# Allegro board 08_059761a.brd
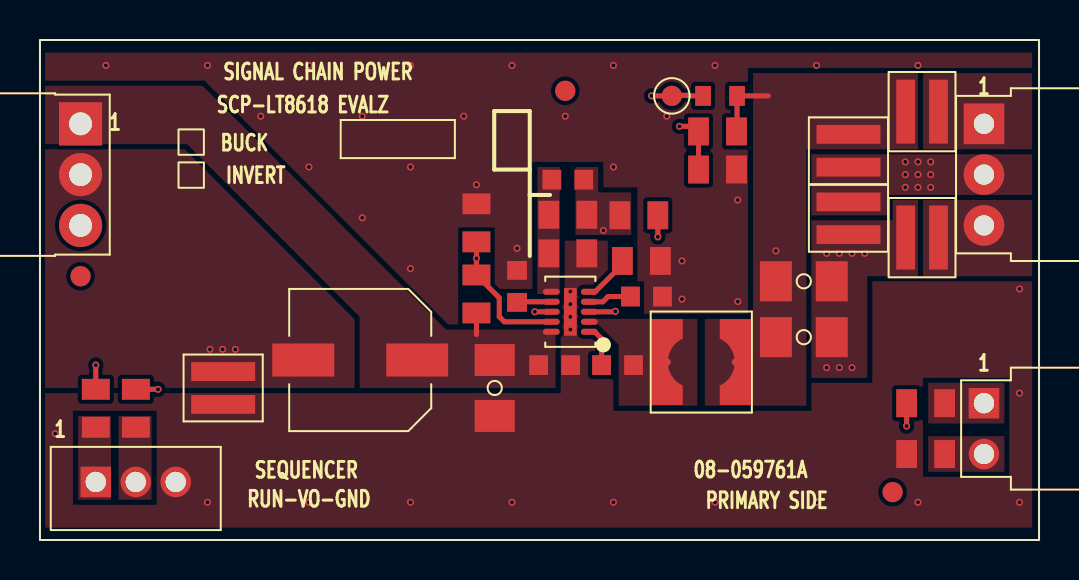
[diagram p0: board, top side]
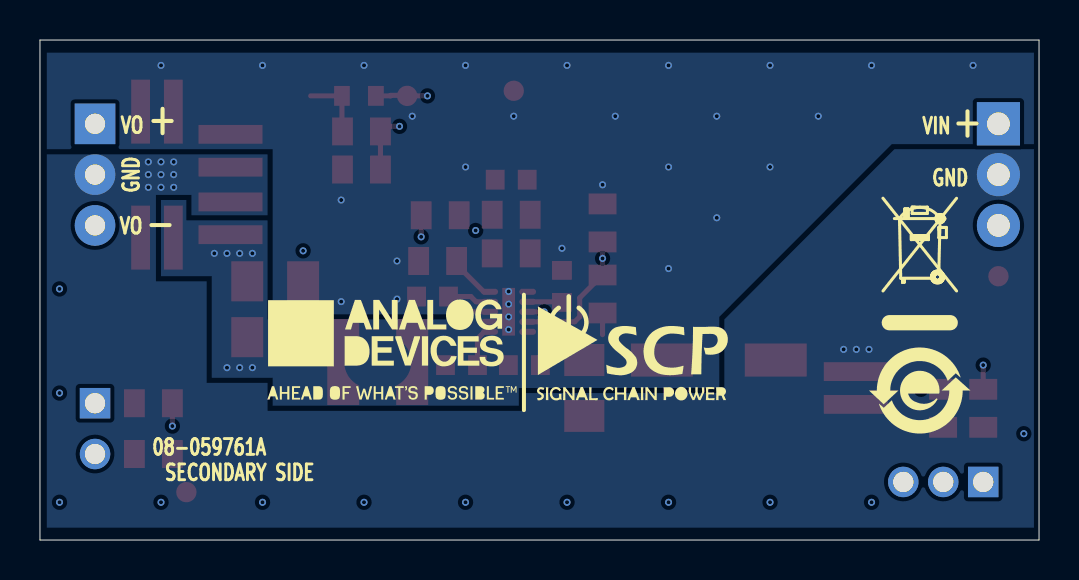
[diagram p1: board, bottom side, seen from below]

Outline 50 x 25 mm; copper layers: TOP, L2_GND, L3_SIGNAL, BOTTOM. Coordinates in mm from the lower left corner of the outline.
Outline path: 0,25 50,25 50,0 0,0 0,25

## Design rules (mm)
constraint set DEFAULT: min track width 0.254

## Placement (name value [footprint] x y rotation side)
C1  22UF  [CPLSMSQ260H315]  16.03 9 180 top
C2  1uF  [C1206H71]  22.76 7.6 270 top
C3  0.1UF  [C0603]  25.76 8.74 0 top
C4  0.047uF  [C0603]  28.91 8.74 0 top
C5  TBD0603  [C0603]  26.42 18.02 0 top
C6  10UF  [C1206H71]  38.23 10.14 0 top
C7  1UF  [C0603]  30.35 12.17 0 top
C8  0.01uF  [C0603]  23.88 12.68 90 top
C9  4.7UF  [C1206H71]  38.23 12.94 0 top
INPUT  PBC03SBAN  [CNTHMHDRRA1X3L300W100H145]  2.03 20.81 270 top
L1  33UH  [LSMSQ150H71]  33.1 8.9 0 top
NOREF  -  []  50 0 90 top
NOREF#2  -  [unnamed#2]  2.03 13.19 0 top
NOREF#3  -  []  90.79 32.31 0 top
NOREF#4  -  []  50 25 0 top
NOREF#5  -  []  0 0 0 top
NOREF#6  -  []  -137.31 -48.38 0 top
NOREF#7  -  []  -197.25 -222.03 0 top
NOREF#8  -  []  50 0 90 top
NOREF#9  -  []  0 0 0 top
NOREF#10  -  []  0 25 0 top
NOREF#11  -  []  50 25 180 top
NOREF#12  -  []  2.03 20.81 0 top
NOREF#13  -  [unnamed#2]  42.67 2.39 0 top
NOREF#14  -  []  -131.19 155.48 0 top
NOREF#15  -  []  77.05 131.34 0 top
NOREF#16  -  []  0 0 0 top
NOREF#17  -  []  44.53 3.99 0 top
NOREF#18  -  [unnamed#2]  26.29 22.46 0 top
NOREF#19  -  []  -197.25 -222.03 0 top
NOREF#20  -  []  0 25 0 top
NOREF#21  -  []  0 25 270 top
NOREF#22  -  []  2.03 20.81 0 top
NOREF#23  -  []  25.51 46.03 0 top
NOREF#24  -  []  -197.25 -222.03 0 top
NOREF#25  -  []  32.67 9.48 180 bottom
NOREF#26  -  []  5.97 7.47 180 bottom
NOREF#27  -  []  6.17 10.55 180 bottom
NOREF#28  -  []  17.55 11.26 180 bottom
NOREF#29  -  []  20.32 9.63 180 bottom
OUTPUT  PPPC031LGBN-RC  [CNHDRRA1X3H108]  47.24 20.81 270 top
P1  53253-0370  [CNTHMHDR1X3L315W144H224]  2.79 2.9 0 top
PG  TESTPAD  [TPSMC40]  31.62 22.21 0 top
R1  1MEG  [R0805]  21.84 12.3 90 top
R2  18.2K  [R0805]  30.1 13.95 0 top
R3  49.9K  [R0603]  34.04 22.21 180 top
R4  1MEG  [R0805]  26.42 16.26 0 top
R5  187K  [R0805]  26.42 14.33 0 top
R6  TBD0805  [R0805]  21.84 15.86 90 top
R7  0  [R0805]  29.97 16.24 180 top
R8  TBD0805  [R0805]  44.32 6.84 0 top
R9  0  [R0805]  33.91 20.43 180 top
R10  TBD0805  [R0805]  33.91 18.52 0 top
R11  TBD0805  [R0805]  2.79 6.59 90 top
R12  TBD0805  [R0805]  4.8 6.59 90 top
R13  TBD0805  [R0805]  44.32 4.3 0 top
R14  0  [R0612]  9.17 7.6 270 top
R15  0  [R0612]  40.46 16.08 90 top
R16  0  [R0612]  44.15 21.42 0 top
R17  0  [R0612]  40.46 19.46 270 top
R18  0  [R0612]  44.15 15.12 0 top
U1  LT8618EDDB#PBF  [DFN10_3X2_PAD2_39X0_64]  26.54 11.41 90 top
VIOC  PPPC021LGBN-RC  [CNTHFHDRRA1X2L220W335H108]  47.24 6.84 270 top

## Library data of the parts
C1 = CAPP: Tolerance: 20; User Part Number: UPN; alternate symbols: (); part number: CAPP_SM-22UF,63V,20,E033596,CPLSMSQ260H315; tolerance: 20
C2 = CAP: Tolerance: 10; User Part Number: UPN; alternate symbols: (); part number: CAP_SM-1UF,100V,10,E023069,C1206H71; tolerance: 10
C3 = CAP: User Part Number: UPN; Tolerance: 10; alternate symbols: (C0603L); part number: CAP_SM-0.1UF,100V,10,E033337,C0603; tolerance: 10
C4 = CAP: User Part Number: UPN; Tolerance: 10; alternate symbols: (); part number: CAP_SM-0.047UF,50V,10,E012649,C0603; tolerance: 10
C5 = CAP: User Part Number: UPN; alternate symbols: (C0603L, C0603L_ALT); part number: CAP_SM-TBD0603,TBD0603,TBD0603,E000382,C0603
C6 = CAP: Tolerance: 20; User Part Number: UPN; alternate symbols: (); part number: CAP_SM-10UF,50V,20,E035601,C1206H71; tolerance: 20
C7 = CAP: User Part Number: UPN; Tolerance: 10; alternate symbols: (); part number: CAP_SM-1UF,10V,10,E033698,C0603; tolerance: 10
C8 = CAP: User Part Number: UPN; Tolerance: 10; alternate symbols: (); part number: CAP_SM-0.01UF,50V,10,E018587,C0603; tolerance: 10
C9 = CAP: Tolerance: 10; User Part Number: UPN; alternate symbols: (); part number: CAP_SM-4.7UF,50V,10,E038262,C1206H71; tolerance: 10
INPUT = CN3P: Tolerance: N/A; User Part Number: UPN; alternate symbols: (CNTHMHDRRA1X3L300W100H145_SCP); part number: CN3P_TH-PBC03SBAN,E034137,CNTHMHDRRA1X3L300W100H145; tolerance: N/A
L1 = IND: User Part Number: UPN; Tolerance: 30; alternate symbols: (); part number: IND_SM-33UH,30,E040015,LSMSQ150H71; tolerance: 30
OUTPUT = CN3P: User Part Number: UPN; Tolerance: N/A; alternate symbols: (CNHDRRA1X3H108_SCP); part number: CN3P_TH-PPPC031LGBN-RC,E034111,CNHDRRA1X3H108; tolerance: N/A
P1 = CN3P: Tolerance: N/A; User Part Number: UPN; alternate symbols: (); part number: CN3P_TH-53253-0370,E033940,CNTHMHDR1X3L315W144H224; tolerance: N/A
PG = NCTESTPAD: Tolerance: N/A; User Part Number: UPN; alternate symbols: (); part number: NCTESTPAD_SM-TESTPAD,E019801,TPSMC40; tolerance: N/A
R1 = RES: User Part Number: UPN; Tolerance: 5; alternate symbols: (); part number: RES_SM-1MEG,E033749,1/8W,5,R0805; tolerance: 5
R2 = RES: User Part Number: UPN; Tolerance: 1; alternate symbols: (R0805L); part number: RES_SM-18.2K,E020752,1/8W,1,R0805; tolerance: 1
R3 = RES: User Part Number: UPN; Tolerance: 1; alternate symbols: (R0603L); part number: RES_SM-49.9K,E015342,1/10W,1,R0603; tolerance: 1
R4 = RES: User Part Number: UPN; Tolerance: 1; alternate symbols: (R0805L); part number: RES_SM-1MEG,E003518,1/8W,1,R0805; tolerance: 1
R5 = RES: User Part Number: UPN; Tolerance: 1; alternate symbols: (R0805L); part number: RES_SM-187K,E015129,1/8W,1,R0805; tolerance: 1
R6 R8 R10-R13 = RES: User Part Number: UPN; alternate symbols: (R0805L); part number: RES_SM-TBD0805,E004051,TBD0805,TBD0805,R0805
R7 R9 = RES: User Part Number: UPN; Tolerance: N/A; alternate symbols: (R0805L); part number: RES_SM-0,E030875,1/8W,N/A,R0805; tolerance: N/A
R14-R18 = RES: User Part Number: UPN; Tolerance: N/A; alternate symbols: (); part number: RES_SM-0,E034651,3/4W,N/A,R0612; tolerance: N/A
U1 = ADLT8618: User Part Number: UPN; Tolerance: N/A; alternate symbols: (); part number: ADLT8618_SM-LT8618EDDB#PBF,E039888,DFN10_3X2_PAD2_39X0_64; tolerance: N/A
VIOC = CN2P: Tolerance: N/A; User Part Number: UPN; alternate symbols: (CNTHFHDRRA1X2L220W335H108_SCP); part number: CN2P_TH-PPPC021LGBN-RC,E034113,CNTHFHDRRA1X2L220W335H108; tolerance: N/A

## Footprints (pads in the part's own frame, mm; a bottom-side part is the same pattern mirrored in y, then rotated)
C0603
  rect 0.94x0.991 smd: 1(-0.8,0) 2(0.8,0)
C1206H71
  rect 1.6x2.007 smd: 1(-1.397,0) 2(1.397,0)
CNHDRRA1X3H108
  rect 2.032x2.032 hole 1.016: 1(0,0)
  round 2.032 hole 1.016: 2(2.54,0) 3(5.08,0)
CNTHFHDRRA1X2L220W335H108
  rect 1.524x1.524 hole 1.016: 1(0,0)
  round 1.524 hole 1.016: 2(2.54,0)
CNTHMHDR1X3L315W144H224
  rect 1.524x1.524 hole 1.016: 1(0,0)
  round 1.524 hole 1.016: 2(2,0) 3(4,0)
CNTHMHDRRA1X3L300W100H145
  rect 2.159x2.159 hole 1.143: 1(0,0)
  round 2.159 hole 1.143: 2(2.54,0) 3(5.08,0)
CPLSMSQ260H315
  rect 3.099x1.651 smd: N(2.85,0) P(-2.85,0)
DFN10_3X2_PAD2_39X0_64
  oval 0.305x0.838 smd: 1(-1,-0.95) 2(-0.5,-0.95) 3(0,-0.95) 4(0.5,-0.95) 5(1,-0.95) 6(1,0.95) 7(0.5,0.95) 8(0,0.95) 9(-0.5,0.95) 10(-1,0.95)
  rect 2.388x0.635 smd: PAD(0,0)
LSMSQ150H71
  custom 0.4x0.4 smd: 1(-1.725,0) 2(1.725,0)
R0603
  rect 0.787x0.991 smd: 1(-0.85,0) 2(0.85,0)
R0612
  rect 0.94x3.2 smd: 1(-0.82,0) 2(0.82,0)
R0805
  rect 1.041x1.397 smd: 1(-0.95,0) 2(0.95,0)
TPSMC40
  round 1.016 smd: 1(0,0)
unnamed#2
  round 1.016 smd: (0,0)

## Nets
GND: C1.N(N2) INPUT.2 OUTPUT.2 R14.1 R15.2(N2) R17.2(N2)
BIAS: R9.2(N2) R10.1 U1.3
PG: PG.1(N1) R3.2(N2) U1.8
RUN: P1.1 R11.1
UNNAMED_2_ADLT8618_I2_BST: C4.1 U1.1
UNNAMED_2_ADLT8618_I2_EN: R1.2(N2) R6.1 R11.2(N2) U1.9
UNNAMED_2_ADLT8618_I2_FB: C5.1 R4.1 R5.1 U1.6
UNNAMED_2_ADLT8618_I2_INTVCC: C7.1 U1.4
UNNAMED_2_ADLT8618_I2_RT: R2.1 U1.5
UNNAMED_2_ADLT8618_I2_SW: C4.2(N2) L1.1 U1.2
UNNAMED_2_ADLT8618_I2_TR: C8.1 U1.7
UNNAMED_2_CAP_I43_N2: C5.2(N2) R4.2(N2) R7.2(N2) R8.1
UNNAMED_2_CN2P_I35_N2: R13.2(N2) VIOC.2(N2)
UNNAMED_2_CN3P_I39_N2: P1.2 R12.1
V+: C1.P C2.1 C3.1 INPUT.1 R1.1 U1.10(VIN)
VIOC: R8.2(N2) VIOC.1
VNEG: C2.2(N2) C3.2(N2) C6.2(N2) C7.2(N2) C8.2(N2) C9.2(N2) P1.3(N3) R2.2(N2) R5.2(N2) R6.2(N2) R10.2(N2) R13.1 R14.2(N2) R15.1 R18.1 U1.PAD
VO+: OUTPUT.1 R12.2(N2) R16.2(N2)
VO-: OUTPUT.3(N3) R18.2(N2)
VPOS: C6.1 C9.1 L1.2(N2) R3.1 R7.1 R9.1 R16.1 R17.1

Pads without a net: INPUT 3

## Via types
v1: diameter 0.356, hole 0.203, TOP to BOTTOM, 71 vias

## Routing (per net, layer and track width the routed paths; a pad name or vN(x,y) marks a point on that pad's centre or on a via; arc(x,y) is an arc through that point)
GND:
  vias: v1(8.51,9.53) v1(9.14,9.53) v1(9.78,9.53) v1(43.31,18.9) v1(43.31,18.27) v1(43.31,17.63) v1(43.94,18.9) v1(43.94,18.27) v1(43.94,17.63) v1(44.58,18.9) v1(44.58,18.27) v1(44.58,17.63)
BIAS: length 14.9
  TOP w0.254: v1(32.01,20.68) 32.71,20.68 R9.2 R10.1 ; v1(28.8,11.44) 28.8,11.41 U1.3
  L3_SIGNAL w0.203: v1(28.8,11.44) 29.59,12.23 29.59,18.27 v1(32.01,20.68)
PG: length 16.6
  TOP w0.254: R3.2 32.46,22.21 32.44,22.23 31.65,22.23 PG.1 v1(30.61,22.21) ; U1.8 v1(24.77,11.41)
  L3_SIGNAL w0.203: v1(30.61,22.21) 30.61,21.57 24.77,15.73 v1(24.77,11.41)
UNNAMED_2_ADLT8618_I2_BST: length 2.1
  TOP w0.254: U1.1 27.76,10.41 28.11,10.07 C4.1
UNNAMED_2_ADLT8618_I2_EN: length 29.4
  TOP w0.254: R11.2 v1(2.79,8.74) ; R6.1 v1(21.84,14.08) R1.2 22.99,12.11 22.99,11.17 23.24,10.91 U1.9
  L3_SIGNAL w0.203: v1(21.84,14.08) 19.43,11.67 5.71,11.67 v1(2.79,8.74)
UNNAMED_2_ADLT8618_I2_INTVCC: length 2.2
  TOP w0.254: C7.1 28.44,12.17 28.17,11.91 U1.4
UNNAMED_2_ADLT8618_I2_RT: length 2.4
  TOP w0.254: U1.5 27.79,12.41 29.15,13.77 R2.1
UNNAMED_2_ADLT8618_I2_TR: length 1.7
  TOP w0.254: U1.7 23.91,11.91 C8.1
UNNAMED_2_CAP_I43_N2: length 24.2
  TOP w0.254: R8.1 v1(43.37,5.7)
  L3_SIGNAL w0.203: v1(28.19,15.48) 27.69,14.97 27.69,10.14 32.13,5.7 v1(43.37,5.7)
V+: length 1.1
  TOP w0.254: R1.1 21.84,10.27
VNEG: length 0
  vias: v1(0.76,5.32) v1(3.3,23.73) v1(8.38,23.73) v1(8.38,1.89) v1(11.05,21.19) v1(13.46,23.73) v1(13.46,18.65) v1(13.46,1.89) v1(16.13,21.19) v1(16.13,16.11) v1(18.54,23.73) v1(18.54,18.65) v1(18.54,13.57) v1(18.54,1.89) v1(21.21,21.19) v1(21.84,17.76) v1(23.62,23.73) v1(23.62,1.89) v1(23.88,14.59) v1(26.29,21.19) v1(26.54,12.43) v1(26.54,11.79) v1(26.54,11.16) v1(26.54,10.52) v1(28.7,23.73) v1(28.7,18.65) v1(28.7,1.89) v1(31.37,21.19) v1(32.13,13.95) v1(32.13,12.05) v1(33.78,23.73) v1(33.78,1.89) v1(34.92,17) v1(34.92,11.92) v1(38.86,23.73) v1(38.86,1.89) v1(39.37,14.33) v1(39.37,8.62) v1(40,14.33) v1(40,8.62) v1(40.64,14.33) v1(40.64,8.62) v1(41.28,14.33) v1(43.94,23.73) v1(43.94,1.89) v1(49.02,12.55) v1(49.02,7.35) v1(49.02,1.89)
VO+: length 58.9
  TOP w0.254: R12.2 v1(5.91,7.54)
  L3_SIGNAL w0.203: OUTPUT.1 45.85,19.41 45.85,6.2 43.31,3.66 9.78,3.66 v1(5.91,7.54)
VPOS: length 10.6
  TOP w0.254: 34.86,20.43 34.89,20.46 R3.1 36.45,22.21 ; R7.1 v1(30.92,15.16)
  L3_SIGNAL w0.203: v1(30.92,15.16) 36.13,15.16 v1(36.83,14.46)

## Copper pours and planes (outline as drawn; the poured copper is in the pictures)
GND on TOP: 0.25,19.54 7.24,19.54 15.75,11.03 15.75,7.6 0.25,7.6
GND on TOP: 49.66,19.29 38.61,19.29 38.61,16.24 42.42,16.24 42.42,17.25 49.66,17.25
GND on BOTTOM, L2_GND: 0.25,19.54 7.24,19.54 15.75,11.03 15.75,7.35 25.78,7.35 25.78,6.46 38.61,6.46 38.61,7.86 41.66,7.86 41.66,12.94 44.2,12.94 44.2,17.25 42.42,17.25 42.42,16.24 38.61,16.24 38.61,19.29 49.66,19.29 49.66,0.62 0.25,0.62
RUN on TOP: 3.56,2.01 1.91,2.01 1.91,6.2 3.56,6.2
UNNAMED_2_ADLT8618_I2_FB on TOP: 26.01,12.3 26.01,18.65 24.89,18.65 24.89,12.3
UNNAMED_2_ADLT8618_I2_SW on TOP: 28.96,9.76 28.96,6.71 32.89,6.71 32.89,11.06 27.3,11.06 27.3,10.78 27.94,10.78
UNNAMED_2_CAP_I43_N2 on TOP: 26.8,18.65 27.94,18.65 27.94,17.38 29.59,17.38 29.59,15.25 26.8,15.25
UNNAMED_2_CN2P_I35_N2 on TOP: 48.26,5.19 48.26,3.41 44.45,3.41 44.45,5.19
UNNAMED_2_CN3P_I39_N2 on TOP: 5.59,2.01 3.94,2.01 3.94,6.2 5.59,6.2
V+ on TOP: 25.81,10.52 20.32,10.52 8.13,22.71 0.25,22.71 0.25,19.79 7.37,19.79 16,11.16 16,7.6 25.81,7.6
VIOC on TOP: 48.26,7.86 48.26,5.82 44.45,5.82 44.45,7.86
VNEG on TOP: 42.67,17 43.94,17 43.94,13.19 41.4,13.19 41.4,8.11 38.61,8.11 38.61,15.98 42.67,15.98
VNEG on TOP: 0.25,0.62 0.25,24.37 49.66,24.37 49.66,0.62 ; 6 cut-outs
VNEG on BOTTOM, L2_GND: 0.25,24.37 49.66,24.37 49.66,19.54 38.35,19.54 38.35,11.28 29.08,11.28 29.08,11.03 38.61,11.03 38.61,15.98 42.67,15.98 42.67,17 43.94,17 43.94,13.19 41.4,13.19 41.4,8.11 38.35,8.11 38.35,6.71 26.04,6.71 26.04,7.6 16,7.6 16,11.16 7.37,19.79 0.25,19.79
VNEG on L3_SIGNAL: 0.25,24.37 49.66,24.37 49.66,0.62 0.25,0.62 ; 2 cut-outs
VO+ on TOP: 49.66,19.54 49.66,23.35 44.2,23.35 44.2,19.54
VO- on TOP: 49.66,17 49.66,13.19 44.2,13.19 44.2,17
VPOS on TOP: 35.69,23.35 43.94,23.35 43.94,19.54 38.35,19.54 38.35,6.71 33.27,6.71 33.27,11.06 35.69,11.06

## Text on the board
Ref Des/Silkscreen Bottom: GND | VIN | 08-059761A | VO | + | -
User.Comments: 4.    RoHS COMPLIANCE: ASSEMBLY VENDOR SHOULD ASSURE COMPLIANCE | WITH LEAD-FREE AND RoHS PCB ASSEMBLY STANDARDS (EU RoHS | DIRECTIVE 2002/95/EC).
Ref Des/Silkscreen Top: BUCK | INVERT | SCP-LT8618 EVALZ | SEQUENCER | RUN-VO-GND | SIGNAL CHAIN POWER
ROOT_NUMBER: 059761
DIMENSION: REF | SEE FAB NOTES 15 | DIA MAX
PAGE_OUTLINE: N/A | A.CAUILAN | K.JABATAN | L EVANGELIO | A.SERQUINA | 05DEC18 | 23OCT19 | 13DEC19 | A | SCP-LT8618 EVALZ | EVALUATION BOARD | -059761
User.15: ROHS COMPLIANCE NOTE:  (Required for Customer Boards) Add to top of MATERIALS | ENIG (Electroless Nickel/Immersion Gold) | PER IPC-4552 LATEST REVISION | HOMOGENOUS MATERIALS IN THIS BOARD SHALL BE COMPLIANT | THE EU RoHS DIRECTIVE 2002/95/EC | INTERNAL LAYERS 1 OZ. COPPER. | 15.    THRU VIAS TO BE FILLED WITH SOLDERMASK.
User.17: L2 GND | 08-      -07
User.18: L3 SIGNAL | 08-      -08
User.23: 1 | A
User.27: 2 | A
User.45: 2 | FIGURE | SIZE | 8.0 | 40.0 | 45.0 | PLATED | FINISHED HOLES IN MILS | ALL UNITS ARE IN MILS | QTY | 71 | 8 | 3 | TOLERANCE/NOTES | EVALUATION BOARD | A
